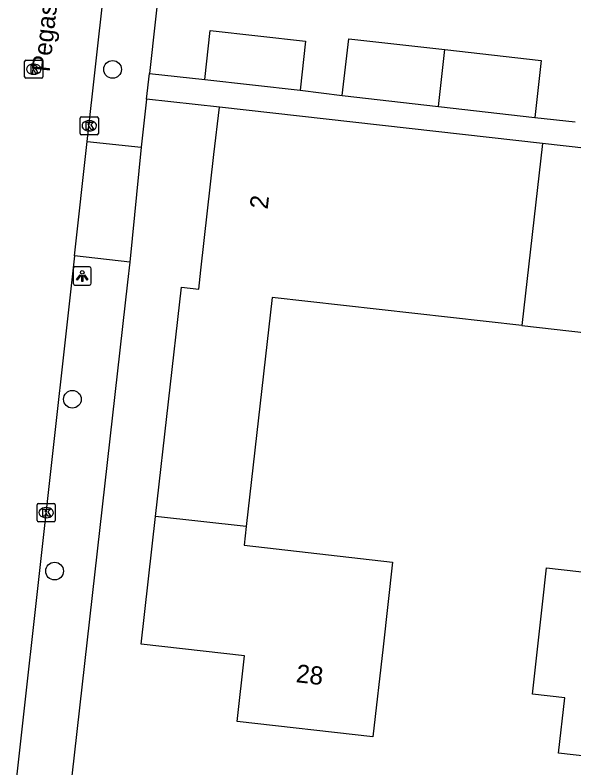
# Model space of a CAD drawing. Extents: x 161928 to 163055, y 386475 to 387428.
# Drawn here: x 162377.68 to 162408.52, y 386852.75 to 386894.32 of the extents above; entities that cross this region are included whole.
import ezdxf

# ---------------------------------------------------------------- set-up
doc = ezdxf.new("R2010")
doc.units = 0
for name, color, linetype in [('IMGEO_Boom', 7, 'Continuous'), ('IMGEO_Kolk', 7, 'Continuous'), ('IMGEO_Lichtpunt', 7, 'Continuous'), ('IMGEO_Openbare_ruimte_label', 7, 'Continuous'), ('IMGEO_Pand', 7, 'Continuous'), ('IMGEO_Pand_nummerreeks', 7, 'Continuous'), ('IMGEO_Rijbaan_lokaal_open', 7, 'Continuous'), ('IMGEO_Rioolput', 7, 'Continuous'), ('IMGEO_Voetpad_open', 7, 'Continuous')]:
    doc.layers.add(name, color=color, linetype=linetype)

msp = doc.modelspace()

# ---------------------------------------------------------------- linework, layer by layer
at = {"layer": 'IMGEO_Boom'}
for centre in [(162383.058, 386891.316), (162380.841, 386873.102), (162379.859, 386863.614)]:
    msp.add_circle(centre, 0.489, dxfattribs=at)
at = {"layer": 'IMGEO_Kolk'}
for p, q in [((162381.274, 386887.775), (162381.274, 386888.627)), ((162381.349, 386888.701), (162382.201, 386888.701)), ((162382.275, 386888.627), (162382.275, 386887.775)), ((162381.762, 386888.481), (162381.787, 386888.481)), ((162381.785, 386887.921), (162381.76, 386887.921)), ((162382.201, 386887.701), (162381.349, 386887.701)), ((162378.896, 386866.417), (162378.896, 386867.269)), ((162378.971, 386867.343), (162379.823, 386867.343)), ((162379.384, 386867.123), (162379.409, 386867.123)), ((162379.897, 386867.269), (162379.897, 386866.417)), ((162379.407, 386866.563), (162379.382, 386866.563)), ((162379.823, 386866.343), (162378.971, 386866.343))]:
    msp.add_line(p, q, dxfattribs=at)
for points in [[(162381.274, 386887.775), (162381.274, 386888.627)], [(162381.349, 386888.701), (162382.201, 386888.701)], [(162382.275, 386888.627), (162382.275, 386887.775)], [(162381.595, 386888.401), (162381.718, 386888.401), (162381.718, 386888.25), (162381.848, 386888.401), (162382.012, 386888.401), (162381.866, 386888.25), (162382.019, 386888.001), (162381.867, 386888.001), (162381.782, 386888.165), (162381.718, 386888.098), (162381.718, 386888.001), (162381.595, 386888.001), (162381.595, 386888.401)], [(162382.201, 386887.701), (162381.349, 386887.701)], [(162378.896, 386866.417), (162378.896, 386867.269)], [(162378.971, 386867.343), (162379.823, 386867.343)], [(162379.217, 386867.043), (162379.34, 386867.043), (162379.34, 386866.892), (162379.47, 386867.043), (162379.634, 386867.043), (162379.488, 386866.892), (162379.641, 386866.643), (162379.489, 386866.643), (162379.404, 386866.807), (162379.34, 386866.74), (162379.34, 386866.643), (162379.217, 386866.643), (162379.217, 386867.043)], [(162379.897, 386867.269), (162379.897, 386866.417)], [(162379.823, 386866.343), (162378.971, 386866.343)]]:
    msp.add_lwpolyline(points, dxfattribs=at)
for centre, start, end in [((162381.351, 386888.625), 91.552, 178.448), ((162381.351, 386888.625), 91.552, 178.448), ((162382.199, 386888.625), 1.552, 88.448), ((162382.199, 386888.625), 1.552, 88.448), ((162381.351, 386887.777), 181.552, 268.448), ((162381.351, 386887.777), 181.552, 268.448), ((162382.199, 386887.777), 271.552, 358.448), ((162382.199, 386887.777), 271.552, 358.448), ((162378.973, 386867.267), 91.552, 178.448), ((162378.973, 386867.267), 91.552, 178.448), ((162379.821, 386867.267), 1.552, 88.448), ((162379.821, 386867.267), 1.552, 88.448), ((162378.973, 386866.419), 181.552, 268.448), ((162378.973, 386866.419), 181.552, 268.448), ((162379.821, 386866.419), 271.552, 358.448), ((162379.821, 386866.419), 271.552, 358.448)]:
    msp.add_arc(centre, 0.0765, start, end, dxfattribs=at)
for centre, major_axis, ratio, start_param, end_param in [((162381.761, 386888.201), (-0.387, 0.002), 0.722429, 4.712389, 7.853982), ((162381.786, 386888.201), (-0.39, 0.002), 0.717154, 1.570796, 4.712389), ((162379.383, 386866.843), (-0.387, 0.002), 0.722429, 4.712389, 7.853982), ((162379.408, 386866.843), (-0.39, 0.002), 0.717154, 1.570796, 4.712389)]:
    msp.add_ellipse(centre, major_axis=major_axis, ratio=ratio, start_param=start_param, end_param=end_param, dxfattribs=at)
at = {"layer": 'IMGEO_Lichtpunt'}
for p, q in [((162380.888, 386880.312), (162380.888, 386879.505)), ((162380.888, 386880.312), (162380.888, 386879.505)), ((162381.79, 386880.407), (162380.982, 386880.407)), ((162381.79, 386880.407), (162380.982, 386880.407)), ((162381.884, 386879.505), (162381.884, 386880.312)), ((162381.884, 386879.505), (162381.884, 386880.312)), ((162380.982, 386879.411), (162381.79, 386879.411)), ((162380.982, 386879.411), (162381.79, 386879.411))]:
    msp.add_line(p, q, dxfattribs=at)
for points in [[(162381.262, 386879.976), (162381.301, 386879.948), (162381.113, 386879.686), (162381.075, 386879.713), (162381.262, 386879.976)], [(162381.364, 386879.928), (162381.411, 386879.928), (162381.411, 386879.606), (162381.364, 386879.606), (162381.364, 386879.928)], [(162381.474, 386879.948), (162381.512, 386879.975), (162381.699, 386879.713), (162381.66, 386879.685), (162381.474, 386879.948)]]:
    msp.add_lwpolyline(points, dxfattribs=at)
msp.add_circle((162381.387, 386880.11), 0.0994, dxfattribs=at)
for centre, start, end in [((162380.982, 386880.312), 90, 180), ((162380.982, 386880.312), 90, 180), ((162381.79, 386880.312), 0, 90), ((162381.79, 386880.312), 0, 90), ((162380.982, 386879.505), 180, 270), ((162380.982, 386879.505), 180, 270), ((162381.79, 386879.505), 270, 0), ((162381.79, 386879.505), 270, 360)]:
    msp.add_arc(centre, 0.0946, start, end, dxfattribs=at)
at = {"layer": 'IMGEO_Pand'}
for points in [[(162388.146, 386890.759), (162388.448, 386893.463), (162393.71, 386892.876), (162393.408, 386890.172)], [(162395.734, 386889.87), (162396.089, 386893.007), (162401.388, 386892.407)], [(162401.036, 386889.27), (162401.388, 386892.407)], [(162401.388, 386892.407), (162406.706, 386891.806), (162406.352, 386888.669)], [(162388.146, 386890.759), (162393.408, 386890.172)], [(162395.734, 386889.87), (162401.036, 386889.27)], [(162385.433, 386866.638), (162386.86, 386879.291), (162387.818, 386879.183), (162387.937, 386880.237), (162388.655, 386886.61), (162388.951, 386889.232)], [(162406.778, 386887.222), (162388.951, 386889.232)], [(162401.036, 386889.27), (162406.352, 386888.669)], [(162406.778, 386887.222), (162405.645, 386877.167)], [(162439.27, 386883.559), (162406.778, 386887.222)], [(162405.645, 386877.167), (162391.858, 386878.722), (162390.433, 386866.075)], [(162405.645, 386877.167), (162410.987, 386876.565)], [(162422.093, 386875.317), (162420.363, 386859.971), (162419.803, 386855.002), (162419.427, 386855.044), (162419.516, 386855.83), (162415.974, 386856.229), (162416.072, 386857.093), (162414.482, 386857.272), (162413.983, 386852.844), (162407.665, 386853.557), (162408.01, 386856.617), (162406.223, 386856.819), (162406.784, 386861.788), (162407.01, 386863.796), (162415.278, 386862.863), (162416.718, 386875.642), (162414.974, 386875.839), (162415.005, 386876.112)], [(162390.433, 386866.075), (162390.316, 386865.04), (162398.51, 386864.116), (162397.982, 386859.435), (162397.422, 386854.466), (162389.939, 386855.31), (162390.347, 386858.931), (162384.637, 386859.575), (162385.433, 386866.638)], [(162390.433, 386866.075), (162385.433, 386866.638)]]:
    msp.add_lwpolyline(points, dxfattribs=at)
at = {"layer": 'IMGEO_Rijbaan_lokaal_open'}
for points in [[(162381.665, 386887.335), (162388.21, 386946.063), (162388.714, 386949.824), (162388.781, 386950.457)], [(162380.96, 386881.013), (162381.665, 386887.335)], [(162380.96, 386881.013), (162377.679, 386851.573)]]:
    msp.add_lwpolyline(points, dxfattribs=at)
at = {"layer": 'IMGEO_Rioolput'}
for p, q in [((162378.207, 386890.9), (162378.207, 386891.752)), ((162378.282, 386891.826), (162379.134, 386891.826)), ((162378.695, 386891.606), (162378.72, 386891.606)), ((162379.208, 386891.752), (162379.208, 386890.9)), ((162379.134, 386890.826), (162378.282, 386890.826)), ((162378.718, 386891.046), (162378.693, 386891.046))]:
    msp.add_line(p, q, dxfattribs=at)
for points in [[(162378.207, 386890.9), (162378.207, 386891.752)], [(162378.282, 386891.826), (162379.134, 386891.826)], [(162378.796, 386891.524), (162378.544, 386891.526), (162378.544, 386891.126)], [(162379.208, 386891.752), (162379.208, 386890.9)], [(162378.544, 386891.126), (162378.668, 386891.126), (162378.668, 386891.288), (162378.679, 386891.288)], [(162378.722, 386891.445), (162378.668, 386891.445), (162378.668, 386891.364)], [(162378.668, 386891.364), (162378.72, 386891.364)], [(162378.726, 386891.259), (162378.797, 386891.126), (162378.937, 386891.126), (162378.872, 386891.252)], [(162379.134, 386890.826), (162378.282, 386890.826)]]:
    msp.add_lwpolyline(points, dxfattribs=at)
for centre, radius, start, end in [((162378.284, 386891.75), 0.0765, 91.552, 178.448), ((162378.284, 386891.75), 0.0765, 91.552, 178.448), ((162378.795, 386891.414), 0.109, 350.3612, 89.416), ((162379.132, 386891.75), 0.0765, 1.552, 88.448), ((162379.132, 386891.75), 0.0765, 1.552, 88.448), ((162378.678, 386891.235), 0.0533, 26.0293, 88.6989), ((162378.704, 386891.553), 0.19, 274.7715, 282.9687), ((162378.728, 386891.349), 0.0964, 77.0061, 93.1865), ((162378.742, 386891.406), 0.0378, 276.6634, 79.6772), ((162378.793, 386891.414), 0.112, 277.5842, 350.9817), ((162378.777, 386891.199), 0.108, 29.5134, 73.7905), ((162378.284, 386890.902), 0.0765, 181.552, 268.448), ((162378.284, 386890.902), 0.0765, 181.552, 268.448), ((162379.132, 386890.902), 0.0765, 271.552, 358.448), ((162379.132, 386890.902), 0.0765, 271.552, 358.448)]:
    msp.add_arc(centre, radius, start, end, dxfattribs=at)
for centre, major_axis, ratio, start_param, end_param in [((162378.694, 386891.326), (-0.387, 0.002), 0.722429, 4.712389, 7.853982), ((162378.719, 386891.326), (-0.39, 0.002), 0.717154, 1.570796, 4.712389)]:
    msp.add_ellipse(centre, major_axis=major_axis, ratio=ratio, start_param=start_param, end_param=end_param, dxfattribs=at)
at = {"layer": 'IMGEO_Voetpad_open'}
for points in [[(162387.517, 386913.102), (162385.091, 386891.096)], [(162384.934, 386889.675), (162385.091, 386891.096)], [(162385.091, 386891.096), (162388.146, 386890.759)], [(162393.408, 386890.172), (162395.734, 386889.87)], [(162384.934, 386889.675), (162384.642, 386887.023)], [(162388.951, 386889.232), (162384.934, 386889.675)], [(162406.352, 386888.669), (162408.587, 386888.422)], [(162381.665, 386887.335), (162384.642, 386887.023)], [(162384.642, 386887.023), (162384.004, 386880.674)], [(162384.004, 386880.674), (162380.96, 386881.013)], [(162384.004, 386880.674), (162383.88, 386879.577), (162380.806, 386852.316)]]:
    msp.add_lwpolyline(points, dxfattribs=at)

# ---------------------------------------------------------------- texts
at = {"layer": 'IMGEO_Openbare_ruimte_label'}
msp.add_text('Pegasusweg', height=1, rotation=83.6282, dxfattribs=at).set_placement((162379.584, 386891.146))
at = {"layer": 'IMGEO_Pand_nummerreeks'}
for s, rotation, p in [('2', 83.5672, (162391.613, 386883.564)), ('28', 353.5649, (162393.145, 386857.485))]:
    msp.add_text(s, height=1, rotation=rotation, dxfattribs=at).set_placement(p)

doc.saveas('drawing.dxf')
